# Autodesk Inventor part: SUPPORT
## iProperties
Created: 2004-11
Part Number: SUPPORT
Document SubType Name: Modeling
Designer: Bruno
Manufacturer: Standard
Standards Organization: Custom
Author: Bruno
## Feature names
1. Base1
